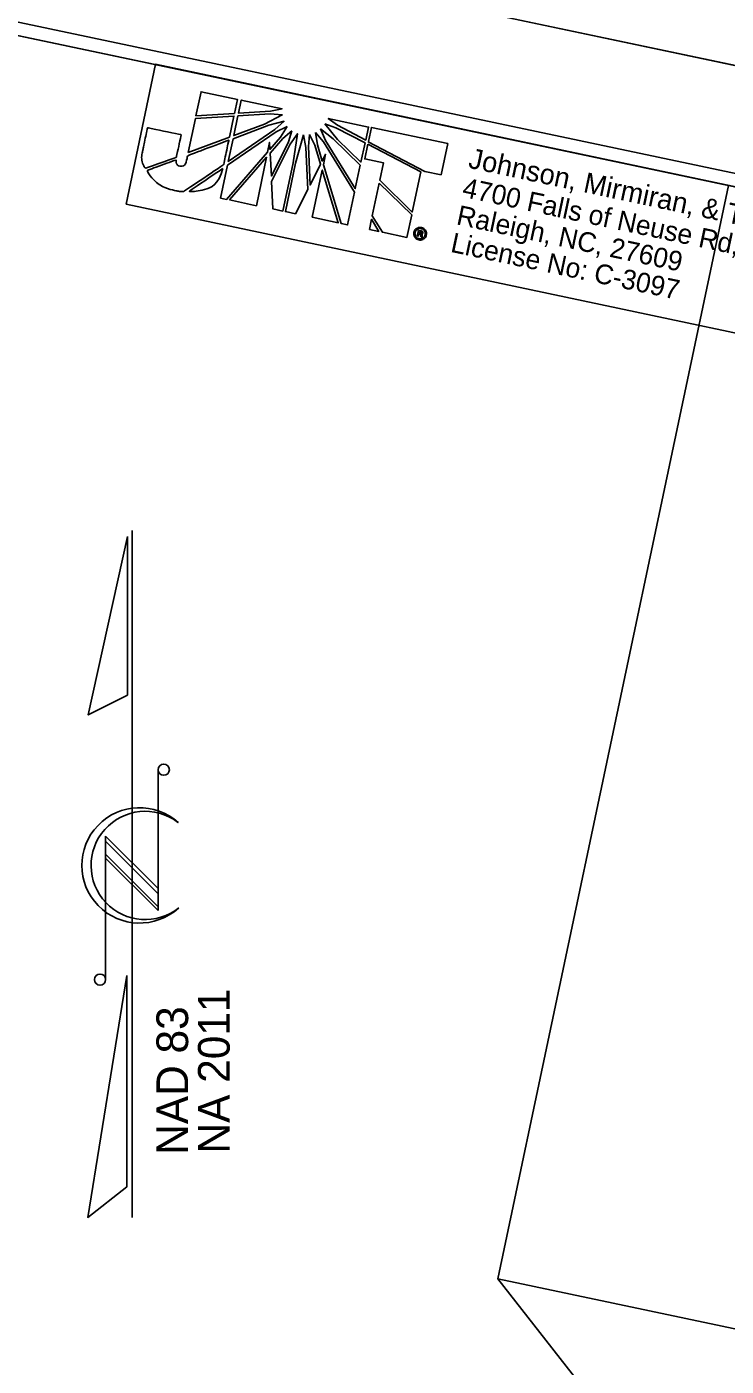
# Model space of a CAD drawing. Extents: x 1636389 to 1804395, y 659763 to 844521.
# Drawn here: x 1637874.5 to 1638006.9, y 843981.4 to 844234.9 of the extents above; entities that cross this region are included whole.
import ezdxf

# ---------------------------------------------------------------- set-up
doc = ezdxf.new("R2010")
doc.units = 0
for name, color, linetype in [('Prop Dimension Text', 7, 'Continuous'), ('Sheet Clip Boundary CELL', 7, 'Continuous'), ('Sheet Cutting Line CELL', 7, 'Continuous'), ('Sheet North Arrow CELL', 7, 'Continuous'), ('Sheet Plan CELL', 7, 'Continuous'), ('Sheet Plan Layout CELL', 7, 'Continuous'), ('Sheet Plot Border Inside CELL', 7, 'Continuous'), ('Sheet Plot Border Outside CELL', 7, 'Continuous')]:
    doc.layers.add(name, color=color, linetype=linetype)

msp = doc.modelspace()

# ---------------------------------------------------------------- linework, layer by layer
at = {"layer": 'Prop Dimension Text'}
for p, q in [((1637907.5, 844222.58), (1637906.54, 844218.02)), ((1637914.37, 844221.13), (1637907.5, 844222.58)), ((1637913.81, 844218.48), (1637914.37, 844221.13)), ((1637915.09, 844221.02), (1637914.57, 844218.56)), ((1637922.82, 844219.39), (1637915.09, 844221.02)), ((1637920.67, 844218.93), (1637922.82, 844219.39)), ((1637906.43, 844217.5), (1637905.08, 844211.09)), ((1637913.71, 844217.98), (1637906.43, 844217.5)), ((1637906.54, 844218.02), (1637913.81, 844218.48)), ((1637912.87, 844214), (1637913.71, 844217.98)), ((1637914.46, 844218.02), (1637913.68, 844214.3)), ((1637920.55, 844218.4), (1637914.46, 844218.02)), ((1637914.57, 844218.56), (1637920.67, 844218.93)), ((1637919.52, 844216.48), (1637922.86, 844218.2)), ((1637923.2, 844217.01), (1637920.3, 844216.24)), ((1637922.86, 844218.2), (1637920.55, 844218.4)), ((1637921.48, 844215.43), (1637923.2, 844217.01)), ((1637930.95, 844216.5), (1637933.33, 844213.53)), ((1637933.01, 844215.78), (1637930.95, 844216.5)), ((1637939.19, 844215.91), (1637931.57, 844217.55)), ((1637931.57, 844217.55), (1637933.31, 844216.24)), ((1637905.08, 844211.09), (1637912.87, 844214)), ((1637921.7, 844215), (1637912.5, 844208.69)), ((1637912.65, 844209.42), (1637921.48, 844215.43)), ((1637920.3, 844216.24), (1637913.55, 844213.7)), ((1637913.68, 844214.3), (1637919.52, 844216.48)), ((1637920.53, 844211.68), (1637922.52, 844214)), ((1637923.82, 844216.02), (1637921.7, 844215)), ((1637922.52, 844214), (1637923.82, 844216.02)), ((1637924.68, 844215.2), (1637922.95, 844213.74)), ((1637924.04, 844213.12), (1637924.68, 844215.2)), ((1637925.74, 844214.65), (1637924.34, 844212.65)), ((1637924.9, 844209.17), (1637925.74, 844214.65)), ((1637926.88, 844214.42), (1637925.39, 844209.07)), ((1637927.32, 844212.03), (1637926.88, 844214.42)), ((1637928.04, 844214.49), (1637927.81, 844212.24)), ((1637929, 844212.47), (1637928.04, 844214.49)), ((1637929.15, 844214.9), (1637929.52, 844212.52)), ((1637930.68, 844213.11), (1637929.15, 844214.9)), ((1637930.13, 844215.56), (1637931.05, 844213.38)), ((1637932.5, 844213.67), (1637930.13, 844215.56)), ((1637938.56, 844212.92), (1637933.01, 844215.78)), ((1637933.31, 844216.24), (1637938.67, 844213.44)), ((1637938.67, 844213.44), (1637939.19, 844215.91)), ((1637939.73, 844215.83), (1637939.17, 844213.18)), ((1637954.17, 844212.79), (1637939.73, 844215.83)), ((1637913.55, 844213.7), (1637912.65, 844209.42)), ((1637920.07, 844211.18), (1637920.45, 844213)), ((1637920.45, 844213), (1637920.53, 844211.68)), ((1637922.95, 844213.74), (1637920.58, 844210.99)), ((1637920.81, 844206.63), (1637924.04, 844213.12)), ((1637924.34, 844212.65), (1637920.84, 844205.63)), ((1637927.71, 844204.07), (1637927.32, 844212.03)), ((1637927.81, 844212.24), (1637928.13, 844204.93)), ((1637930.1, 844208.87), (1637929, 844212.47)), ((1637929.52, 844212.52), (1637930.42, 844209.48)), ((1637936.54, 844203.56), (1637930.68, 844213.11)), ((1637931.05, 844213.38), (1637936.69, 844204.28)), ((1637937.62, 844208.68), (1637932.5, 844213.67)), ((1637933.33, 844213.53), (1637937.75, 844209.29)), ((1637937.75, 844209.29), (1637938.56, 844212.92)), ((1637939.06, 844212.65), (1637938.47, 844209.88)), ((1637939.07, 844212.69), (1637939.06, 844212.65)), ((1637949.07, 844207.42), (1637939.07, 844212.69)), ((1637939.17, 844213.18), (1637939.15, 844213.1)), ((1637939.15, 844213.1), (1637949.85, 844207.52)), ((1637952.93, 844206.88), (1637954.17, 844212.79)), ((1637912.32, 844202.22), (1637920.07, 844211.18)), ((1637919.86, 844210.2), (1637912.85, 844202.11)), ((1637917.98, 844201.03), (1637919.86, 844210.2)), ((1637920.58, 844210.99), (1637920.81, 844206.63)), ((1637922.97, 844200.01), (1637924.9, 844209.17)), ((1637925.39, 844209.07), (1637923.46, 844199.91)), ((1637930.42, 844209.48), (1637931.06, 844210.77)), ((1637931.06, 844210.77), (1637930.64, 844208.76)), ((1637938.47, 844209.88), (1637942, 844209.14)), ((1637942, 844209.14), (1637941.31, 844205.84)), ((1637912.5, 844208.69), (1637911.19, 844202.46)), ((1637928.13, 844204.93), (1637930.1, 844208.87)), ((1637930.43, 844207.77), (1637928.55, 844198.84)), ((1637933.47, 844197.8), (1637930.43, 844207.77)), ((1637930.64, 844208.76), (1637934.03, 844197.65)), ((1637936.69, 844204.28), (1637937.62, 844208.68)), ((1637947.48, 844199.83), (1637949.07, 844207.42)), ((1637949.85, 844207.52), (1637952.93, 844206.88)), ((1637920.84, 844205.63), (1637921.09, 844200.41)), ((1637925.36, 844199.51), (1637927.71, 844204.07)), ((1637941.19, 844205.27), (1637939.89, 844199.13)), ((1637947.36, 844199.3), (1637941.19, 844205.27)), ((1637941.31, 844205.84), (1637947.48, 844199.83)), ((1637911.19, 844202.46), (1637912.32, 844202.22)), ((1637912.85, 844202.11), (1637917.98, 844201.03)), ((1637935.24, 844197.4), (1637936.54, 844203.56)), ((1637921.09, 844200.41), (1637922.97, 844200.01)), ((1637923.46, 844199.91), (1637925.36, 844199.51)), ((1637928.55, 844198.84), (1637933.47, 844197.8)), ((1637939.89, 844199.13), (1637941.81, 844196.01)), ((1637946.47, 844195.03), (1637947.36, 844199.3)), ((1637934.03, 844197.65), (1637935.24, 844197.4)), ((1637939.75, 844198.46), (1637939.35, 844196.53)), ((1637939.35, 844196.53), (1637941.13, 844196.16)), ((1637941.13, 844196.16), (1637939.75, 844198.46)), ((1637948.41, 844195.3), (1637948.63, 844196.35)), ((1637948.63, 844196.35), (1637949.06, 844196.26)), ((1637949.06, 844196.26), (1637949.02, 844196.06)), ((1637949.02, 844196.06), (1637949.06, 844196.26)), ((1637949.06, 844196.26), (1637949.13, 844196.25)), ((1637949.19, 844196.88), (1637949.15, 844196.66)), ((1637949.15, 844196.66), (1637949.19, 844196.88)), ((1637941.81, 844196.01), (1637946.47, 844195.03)), ((1637948.65, 844195.25), (1637948.41, 844195.3)), ((1637948.74, 844195.66), (1637948.65, 844195.25)), ((1637948.76, 844194.8), (1637948.71, 844194.57)), ((1637948.71, 844194.57), (1637948.76, 844194.8)), ((1637948.72, 844194.57), (1637948.71, 844194.57)), ((1637948.93, 844195.62), (1637948.74, 844195.66)), ((1637948.76, 844194.8), (1637948.77, 844194.8)), ((1637948.83, 844196.1), (1637948.78, 844195.85)), ((1637948.78, 844195.85), (1637948.97, 844195.81)), ((1637949.02, 844196.06), (1637948.83, 844196.1)), ((1637948.97, 844195.81), (1637948.93, 844195.62)), ((1637948.93, 844195.62), (1637948.97, 844195.81)), ((1637948.94, 844195.62), (1637948.93, 844195.62)), ((1637948.97, 844195.81), (1637948.98, 844195.81)), ((1637949.05, 844196.06), (1637949.02, 844196.06))]:
    msp.add_line(p, q, dxfattribs=at)
msp.add_lwpolyline([(1637893.3, 844201.3), (1638040.08, 844170.28), (1638045.68, 844196.77), (1637898.89, 844227.79)], close=True, dxfattribs=at)
for points in [[(1637906.54, 844218.02), (1637913.81, 844218.48), (1637914.37, 844221.13), (1637907.5, 844222.58), (1637906.54, 844218.02)], [(1637920.67, 844218.93), (1637922.82, 844219.39), (1637915.09, 844221.02), (1637914.57, 844218.56), (1637920.67, 844218.93)], [(1637905.08, 844211.09), (1637912.87, 844214), (1637913.71, 844217.98), (1637906.43, 844217.5), (1637905.08, 844211.09)], [(1637913.55, 844213.7), (1637912.65, 844209.42), (1637921.48, 844215.43), (1637923.2, 844217.01), (1637920.3, 844216.24), (1637913.55, 844213.7)], [(1637914.46, 844218.02), (1637913.68, 844214.3), (1637919.52, 844216.48), (1637922.86, 844218.2), (1637920.55, 844218.4), (1637914.46, 844218.02)], [(1637930.95, 844216.5), (1637933.33, 844213.53), (1637937.75, 844209.29), (1637938.56, 844212.92), (1637933.01, 844215.78), (1637930.95, 844216.5)], [(1637933.31, 844216.24), (1637938.67, 844213.44), (1637939.19, 844215.91), (1637931.57, 844217.55), (1637933.31, 844216.24)], [(1637923.82, 844216.02), (1637921.7, 844215), (1637912.5, 844208.69), (1637911.19, 844202.46), (1637912.32, 844202.22), (1637920.07, 844211.18), (1637920.45, 844213), (1637920.53, 844211.68), (1637922.52, 844214), (1637923.82, 844216.02)], [(1637924.68, 844215.2), (1637922.95, 844213.74), (1637920.58, 844210.99), (1637920.81, 844206.63), (1637924.04, 844213.12), (1637924.68, 844215.2)], [(1637924.34, 844212.65), (1637920.84, 844205.63), (1637921.09, 844200.41), (1637922.97, 844200.01), (1637924.9, 844209.17), (1637925.74, 844214.65), (1637924.34, 844212.65)], [(1637926.88, 844214.42), (1637925.39, 844209.07), (1637923.46, 844199.91), (1637925.36, 844199.51), (1637927.71, 844204.07), (1637927.32, 844212.03), (1637926.88, 844214.42)], [(1637928.04, 844214.49), (1637927.81, 844212.24), (1637928.13, 844204.93), (1637930.1, 844208.87), (1637929, 844212.47), (1637928.04, 844214.49)], [(1637929.15, 844214.9), (1637929.52, 844212.52), (1637930.42, 844209.48), (1637931.06, 844210.77), (1637930.64, 844208.76), (1637934.03, 844197.65), (1637935.24, 844197.4), (1637936.54, 844203.56), (1637930.68, 844213.11), (1637929.15, 844214.9)], [(1637930.13, 844215.56), (1637931.05, 844213.38), (1637936.69, 844204.28), (1637937.62, 844208.68), (1637932.5, 844213.67), (1637930.13, 844215.56)], [(1637954.17, 844212.79), (1637939.73, 844215.83), (1637939.17, 844213.18), (1637939.15, 844213.1), (1637949.85, 844207.52), (1637952.93, 844206.88), (1637954.17, 844212.79)], [(1637939.07, 844212.69), (1637939.06, 844212.65), (1637938.47, 844209.88), (1637942, 844209.14), (1637941.31, 844205.84), (1637947.48, 844199.83), (1637949.07, 844207.42), (1637939.07, 844212.69)], [(1637912.85, 844202.11), (1637917.98, 844201.03), (1637919.86, 844210.2), (1637912.85, 844202.11)], [(1637928.55, 844198.84), (1637933.47, 844197.8), (1637930.43, 844207.77), (1637928.55, 844198.84)], [(1637941.19, 844205.27), (1637939.89, 844199.13), (1637941.81, 844196.01), (1637946.47, 844195.03), (1637947.36, 844199.3), (1637941.19, 844205.27), (1637941.19, 844205.27)], [(1637939.35, 844196.53), (1637939.35, 844196.53), (1637941.13, 844196.16), (1637939.75, 844198.46), (1637939.35, 844196.53)], [(1637949.35, 844195.36), (1637949.34, 844195.31), (1637949.34, 844195.27), (1637949.34, 844195.23), (1637949.34, 844195.11), (1637949.12, 844195.15)]]:
    msp.add_lwpolyline(points, dxfattribs=at)
for points, degree in [([(1637903.73, 844214.46), (1637903.73, 844214.46), (1637897.37, 844215.79), (1637897.37, 844215.79), (1637897.37, 844215.79), (1637896.53, 844211.81), (1637896.53, 844211.81), (1637896.53, 844211.81), (1637896.44, 844211.39), (1637896.44, 844211.39), (1637896.18, 844210.15), (1637896.38, 844209.07), (1637896.93, 844208.09), (1637896.93, 844208.09), (1637902.83, 844210.17), (1637902.84, 844210.25), (1637902.84, 844210.25), (1637903.73, 844214.46), (1637903.73, 844214.46)], 3), ([(1637903.51, 844208.52), (1637903.1, 844208.61), (1637902.8, 844208.91), (1637902.81, 844209.7), (1637902.81, 844209.7), (1637897.24, 844207.69), (1637897.24, 844207.69), (1637898.42, 844205.77), (1637900.65, 844204.31), (1637902.7, 844203.87), (1637903.23, 844203.76), (1637903.65, 844203.72), (1637904.24, 844203.72), (1637904.24, 844203.72), (1637911.78, 844208.81), (1637911.78, 844208.81), (1637911.78, 844208.81), (1637912.75, 844213.43), (1637912.75, 844213.43), (1637912.75, 844213.43), (1637904.96, 844210.51), (1637904.96, 844210.51), (1637904.6, 844208.78), (1637904.08, 844208.4), (1637903.51, 844208.52)], 3), ([(1637903.51, 844208.52), (1637903.1, 844208.61), (1637902.8, 844208.91), (1637902.81, 844209.7), (1637902.81, 844209.7), (1637897.24, 844207.69), (1637897.24, 844207.69), (1637898.42, 844205.77), (1637900.65, 844204.31), (1637902.7, 844203.87), (1637903.23, 844203.76), (1637903.65, 844203.72), (1637904.24, 844203.72), (1637904.24, 844203.72), (1637911.78, 844208.81), (1637911.78, 844208.81), (1637911.78, 844208.81), (1637912.75, 844213.43), (1637912.75, 844213.43), (1637912.75, 844213.43), (1637904.96, 844210.51), (1637904.96, 844210.51), (1637904.6, 844208.78), (1637904.08, 844208.4), (1637903.51, 844208.52)], 3), ([(1637911.62, 844208.08), (1637911.62, 844208.08), (1637905.11, 844203.69), (1637905.11, 844203.69), (1637907.87, 844203.78), (1637910.84, 844204.97), (1637911.62, 844208.08)], 3), ([(1637948.71, 844194.57), (1637948.39, 844194.64), (1637948.14, 844194.81), (1637947.96, 844195.09), (1637947.78, 844195.36), (1637947.72, 844195.66), (1637947.79, 844195.98), (1637947.86, 844196.31), (1637948.03, 844196.56), (1637948.3, 844196.72), (1637948.58, 844196.89), (1637948.87, 844196.95), (1637949.19, 844196.88)], 3), ([(1637949.15, 844196.66), (1637948.89, 844196.72), (1637948.65, 844196.68), (1637948.44, 844196.54), (1637948.22, 844196.4), (1637948.07, 844196.19), (1637948.02, 844195.93), (1637947.96, 844195.68), (1637948.01, 844195.43), (1637948.15, 844195.21), (1637948.3, 844194.99), (1637948.5, 844194.86), (1637948.76, 844194.8)], 3), ([(1637948.77, 844194.8), (1637949.02, 844194.75), (1637949.26, 844194.78), (1637949.48, 844194.93), (1637949.7, 844195.07), (1637949.84, 844195.28), (1637949.9, 844195.54), (1637949.95, 844195.8), (1637949.91, 844196.05), (1637949.76, 844196.26), (1637949.62, 844196.48), (1637949.42, 844196.61), (1637949.15, 844196.66)], 3), ([(1637949.13, 844196.25), (1637949.4, 844196.19), (1637949.51, 844196.06), (1637949.47, 844195.85), (1637949.45, 844195.75), (1637949.39, 844195.68), (1637949.29, 844195.65)], 3), ([(1637949.19, 844196.88), (1637949.52, 844196.81), (1637949.77, 844196.64), (1637949.96, 844196.37), (1637950.14, 844196.12), (1637950.2, 844195.81), (1637950.13, 844195.49)], 3), ([(1637950.13, 844195.49), (1637950.06, 844195.17), (1637949.89, 844194.91), (1637949.62, 844194.73), (1637949.34, 844194.56), (1637949.04, 844194.5), (1637948.72, 844194.57)], 3), ([(1637949.11, 844195.54), (1637949.09, 844195.57), (1637949.03, 844195.6), (1637948.94, 844195.62)], 2), ([(1637948.98, 844195.81), (1637949.13, 844195.78), (1637949.22, 844195.81), (1637949.24, 844195.9), (1637949.25, 844195.97), (1637949.19, 844196.03), (1637949.05, 844196.06)], 3), ([(1637949.12, 844195.15), (1637949.1, 844195.22), (1637949.1, 844195.28), (1637949.11, 844195.35), (1637949.13, 844195.45), (1637949.14, 844195.51), (1637949.11, 844195.54)], 3), ([(1637949.29, 844195.65), (1637949.35, 844195.59), (1637949.37, 844195.5), (1637949.35, 844195.36)], 2)]:
    msp.add_open_spline(points, degree=degree, dxfattribs=at)
at = {"layer": 'Sheet Clip Boundary CELL'}
msp.add_lwpolyline([(1636605.88, 843427.4), (1637975.74, 843138.4), (1637933.22, 843216.08), (1637972.57, 843309.02), (1638006.91, 843302.19), (1638028.95, 843389.18), (1638110.62, 843766.5), (1638114.85, 843806.98), (1638084.44, 843843.65), (1637963.65, 843997.92), (1638007.31, 844204.85), (1636822.64, 844454.79)], close=True, dxfattribs=at)
at = {"layer": 'Sheet Cutting Line CELL'}
msp.add_line((1638262.69, 844173.95), (1636615.46, 844521.48), dxfattribs=at)
at = {"layer": 'Sheet North Arrow CELL'}
for p, q in [((1637894.48, 844009.55), (1637894.48, 844139.55)), ((1637899.38, 844094.31), (1637899.38, 844067.63)), ((1637903.06, 844084.37), (1637903.2, 844084.27)), ((1637899.38, 844071.79), (1637889.44, 844081.73)), ((1637889.44, 844081.73), (1637889.44, 844054.61)), ((1637899.38, 844070.81), (1637889.44, 844080.75)), ((1637889.44, 844080.75), (1637889.44, 844078.31)), ((1637899.38, 844068.37), (1637889.44, 844078.31)), ((1637889.44, 844078.31), (1637899.38, 844068.37)), ((1637899.38, 844067.63), (1637889.44, 844077.57)), ((1637899.38, 844068.37), (1637899.38, 844070.81))]:
    msp.add_line(p, q, dxfattribs=at)
for points in [[(1637893.58, 844138.41), (1637886.16, 844104.65), (1637893.58, 844108.41)], [(1637893.42, 844055.35), (1637886.06, 844009.55), (1637893.42, 844015.35)]]:
    msp.add_lwpolyline(points, close=True, dxfattribs=at)
for centre in [(1637900.44, 844094.29), (1637888.38, 844054.57)]:
    msp.add_circle(centre, 1.06, dxfattribs=at)
for centre, radius, start, end in [((1637895.86, 844076.18), 10.92, 47.84, 312.3941), ((1637896.92, 844076.18), 10.24, 53.095, 308.6287)]:
    msp.add_arc(centre, radius, start, end, dxfattribs=at)
at = {"layer": 'Sheet Plan CELL'}
for points in [[(1638241.44, 844155.45), (1636773.71, 844465.11), (1636556.96, 843437.72), (1638024.67, 843128.08)], [(1636556.96, 843437.72), (1636773.69, 844465.09), (1638045.68, 844196.77), (1638014.71, 844049.94), (1638210.44, 844008.63), (1638024.67, 843128.08)]]:
    msp.add_lwpolyline(points, close=True, dxfattribs=at)
at = {"layer": 'Sheet Plan Layout CELL'}
for points in [[(1636773.69, 844465.09), (1636556.96, 843437.72), (1638024.65, 843128.08), (1638197.75, 843948.53), (1637963.65, 843997.92), (1638007.31, 844204.85)], [(1637963.65, 843997.92), (1638197.77, 843948.52), (1638241.46, 844155.45), (1638007.31, 844204.85)]]:
    msp.add_lwpolyline(points, close=True, dxfattribs=at)
at = {"layer": 'Sheet Plot Border Inside CELL'}
msp.add_lwpolyline([(1636406.26, 843466.95), (1638036.37, 843123.05), (1638254.16, 844155.31), (1636624.05, 844499.23)], close=True, dxfattribs=at)
at = {"layer": 'Sheet Plot Border Outside CELL'}
msp.add_lwpolyline([(1636389.41, 843450.07), (1638036.65, 843102.54), (1638262.69, 844173.95), (1636615.46, 844521.48)], close=True, dxfattribs=at)

# ---------------------------------------------------------------- texts
at = {"layer": 'Prop Dimension Text'}
for s, height, p in [('Johnson, Mirmiran, & Thompson Inc.', 3.8334, (1637957.91, 844208.23)), ('4700 Falls of Neuse Rd, Suite 100, ', 3.7239, (1637956.75, 844202.73)), ('Raleigh, NC, 27609', 3.7239, (1637955.65, 844197.52)), ('License No: C-3097', 3.7239, (1637954.55, 844192.32))]:
    msp.add_text(s, height=height, rotation=348.0661, dxfattribs=at).set_placement(p)
at = {"layer": 'Sheet North Arrow CELL'}
for s, p in [('NA 2011', (1637912.92, 844021.66)), ('NAD 83', (1637905.05, 844021.42))]:
    msp.add_text(s, height=6, rotation=90, dxfattribs=at).set_placement(p)

doc.saveas('drawing.dxf')
